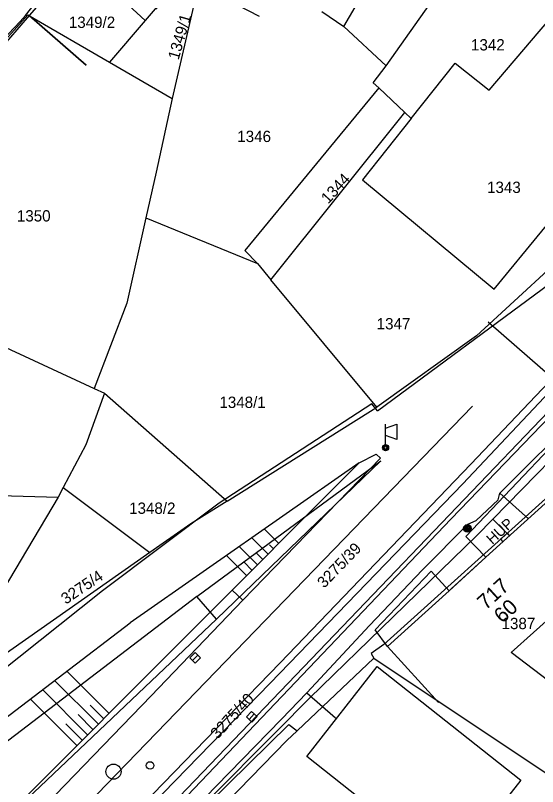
# Model space of a CAD drawing. Extents: x -601580 to 4, y -1204314 to 4.
# Drawn here: x -600174.7 to -600140.2, y -1203683.1 to -1203632.1 of the extents above; entities that cross this region are included whole.
import ezdxf

# ---------------------------------------------------------------- set-up
doc = ezdxf.new("R2010")
doc.units = 0
for name, color, linetype in [('00-INNOGY-NTL', 7, 'Continuous'), ('00-KN-HRANICE PARCEL', 7, 'Continuous'), ('00-KN-PARC. CISLA', 7, 'Continuous'), ('00-KN-VNITRNI KRESBA', 7, 'Continuous'), ('00-POLOHOPIS', 7, 'Continuous'), ('00-SITE KOM. KABEL', 7, 'Continuous'), ('00-VAK-KANAL-POTRUBI', 7, 'Continuous'), ('00-VAK-VODA-RAD IGIS', 7, 'Continuous'), ('Vrstva 25', 7, 'Continuous'), ('Vrstva 27', 7, 'Continuous'), ('Vrstva 28', 7, 'Continuous'), ('Vrstva 33', 7, 'Continuous')]:
    doc.layers.add(name, color=color, linetype=linetype)

# ---------------------------------------------------------------- blocks, each defined once
blk = doc.blocks.new('6.20_44')
at = {"layer": 'Vrstva 27'}
blk.add_circle((0, 0), 0.5, dxfattribs=at)
blk = doc.blocks.new('6.30_62')
at = {"layer": 'Vrstva 27'}
blk.add_line((-0.25, 0), (0.25, 0), dxfattribs=at)
blk.add_lwpolyline([(-0.25, -0.25), (0.25, -0.25), (0.25, 0.25), (-0.25, 0.25)], close=True, dxfattribs=at)
blk = doc.blocks.new('6.30_64')
at = {"layer": 'Vrstva 27'}
blk.add_line((-0.25, 0), (0.25, 0), dxfattribs=at)
blk.add_lwpolyline([(-0.249, -0.25), (0.25, -0.249), (0.249, 0.25), (-0.25, 0.249)], close=True, dxfattribs=at)
blk = doc.blocks.new('6.01A_978')
at = {"layer": 'Vrstva 25'}
for radius in [0.25, 0.2, 0.15, 0.1, 0.05]:
    blk.add_circle((0, 0), radius, dxfattribs=at)
blk = doc.blocks.new('6.790_6')
at = {"layer": 'Vrstva 33'}
blk.add_line((0, 0.2), (0, 1.55), dxfattribs=at)
blk.add_lwpolyline([(0, 1.3), (0.75, 1.55), (0.75, 0.55), (0, 0.8)], dxfattribs=at)
for radius in [0.2, 0.145, 0.0876]:
    blk.add_circle((0, 0), radius, dxfattribs=at)
blk = doc.blocks.new('6.14A_522')
at = {"layer": 'Vrstva 28'}
blk.add_circle((0, 0), 0.25, dxfattribs=at)

msp = doc.modelspace()

# ---------------------------------------------------------------- linework, layer by layer
at = {"layer": '00-INNOGY-NTL'}
for p, q in [((-600136.43, -1203658.56), (-600143.48, -1203652.41)), ((-600143.17, -1203665.46), (-600142.12, -1203666.48))]:
    msp.add_line(p, q, dxfattribs=at)
msp.add_lwpolyline([(-600200.95, -1203725.85), (-600196.18, -1203720.42), (-600193.88, -1203717.79), (-600186.44, -1203709.69), (-600186.02, -1203709.24), (-600180.47, -1203703.4), (-600170.3, -1203692.68), (-600170.15, -1203692.52), (-600164.54, -1203686.62), (-600164.32, -1203686.4), (-600162.46, -1203684.51), (-600162.1, -1203684.15), (-600157.4, -1203679.43), (-600155.29, -1203677.3), (-600144.23, -1203666.53), (-600143.17, -1203665.46), (-600136.43, -1203658.56)], dxfattribs=at)
at = {"layer": '00-KN-HRANICE PARCEL'}
for p, q in [((-600162.01, -1203627.4), (-600164.38, -1203637.6)), ((-600150.21, -1203635.45), (-600144.37, -1203627.17)), ((-600166.16, -1203632.44), (-600170.63, -1203628.32)), ((-600164.22, -1203630.17), (-600166.16, -1203632.44)), ((-600173.93, -1203632.06), (-600185.82, -1203645.47)), ((-600173.93, -1203632.06), (-600168.52, -1203635.2)), ((-600154.48, -1203631.86), (-600153.01, -1203632.85)), ((-600166.16, -1203632.44), (-600168.52, -1203635.2)), ((-600153.01, -1203632.85), (-600150.21, -1203635.45)), ((-600168.52, -1203635.2), (-600164.38, -1203637.6)), ((-600148.98, -1203638.54), (-600150.71, -1203636.91)), ((-600157.84, -1203649.61), (-600148.98, -1203638.54)), ((-600148.98, -1203638.54), (-600148.56, -1203638.94)), ((-600166.11, -1203645.51), (-600167.38, -1203651.16)), ((-600166.11, -1203645.51), (-600158.73, -1203648.54)), ((-600158.73, -1203648.54), (-600157.84, -1203649.61)), ((-600139.25, -1203648.73), (-600144.24, -1203653.31)), ((-600150.83, -1203658.04), (-600157.84, -1203649.61)), ((-600167.38, -1203651.16), (-600169.54, -1203656.81)), ((-600144.24, -1203653.31), (-600150.83, -1203658.04)), ((-600168.84, -1203657.12), (-600170.09, -1203660.52)), ((-600169.54, -1203656.81), (-600168.84, -1203657.12)), ((-600168.84, -1203657.12), (-600160.73, -1203664.25)), ((-600170.09, -1203660.52), (-600171.58, -1203663.36)), ((-600171.58, -1203663.36), (-600171.92, -1203664)), ((-600171.58, -1203663.36), (-600165.85, -1203667.66)), ((-600165.85, -1203667.66), (-600181.89, -1203678.92)), ((-600162.74, -1203670.57), (-600199.85, -1203698.89)), ((-600161.44, -1203672.08), (-600162.74, -1203670.57)), ((-600195.59, -1203704.46), (-600161.44, -1203672.08)), ((-600151.04, -1203674.64), (-600156.1, -1203679.45))]:
    msp.add_line(p, q, dxfattribs=at)
for points in [[(-600148.56, -1203638.94), (-600145.65, -1203635.27), (-600143.4, -1203637.06), (-600138.31, -1203631.06)], [(-600148.56, -1203638.94), (-600151.79, -1203642.99), (-600143.07, -1203650.23), (-600136.77, -1203642.56), (-600138.82, -1203640.83), (-600133.83, -1203634.63)], [(-600150.71, -1203636.91), (-600151.07, -1203636.57), (-600150.21, -1203635.45)], [(-600150.71, -1203636.91), (-600159.57, -1203647.66), (-600158.73, -1203648.54)], [(-600164.38, -1203637.6), (-600165.43, -1203642.49), (-600166.11, -1203645.51)], [(-600185.82, -1203645.47), (-600185.53, -1203645.67), (-600176.3, -1203653.67), (-600169.54, -1203656.81)], [(-600160.73, -1203664.25), (-600151.26, -1203658.31), (-600150.83, -1203658.04)], [(-600162.74, -1203670.57), (-600150.57, -1203661.58), (-600161.44, -1203672.08)], [(-600194.85, -1203661.79), (-600187.88, -1203663.53), (-600185.06, -1203663.61), (-600171.92, -1203664)], [(-600171.92, -1203664), (-600176.84, -1203672.24), (-600181.89, -1203678.92)], [(-600160.73, -1203664.25), (-600163.13, -1203665.75), (-600165.85, -1203667.66)], [(-600139.09, -1203664.18), (-600139.46, -1203663.9), (-600150.38, -1203673.74), (-600151.22, -1203674.34), (-600151.04, -1203674.64)], [(-600151.04, -1203674.64), (-600132.68, -1203686.89), (-600131.82, -1203687.3)], [(-600165.95, -1203688.2), (-600156.65, -1203679.03), (-600156.1, -1203679.45)], [(-600156.1, -1203679.45), (-600156.78, -1203680.09), (-600162.34, -1203685.81)]]:
    msp.add_lwpolyline(points, dxfattribs=at)
at = {"layer": '00-KN-VNITRNI KRESBA'}
for p, q in [((-600153.01, -1203632.85), (-600148.08, -1203624.29)), ((-600141.94, -1203674.28), (-600138.94, -1203671.57)), ((-600130.54, -1203683.01), (-600141.94, -1203674.28)), ((-600155.47, -1203681.16), (-600150.81, -1203675.2)), ((-600150.81, -1203675.2), (-600141.32, -1203682.73)), ((-600145.99, -1203688.65), (-600155.47, -1203681.16)), ((-600141.32, -1203682.73), (-600145.99, -1203688.65))]:
    msp.add_line(p, q, dxfattribs=at)
at = {"layer": '00-POLOHOPIS'}
for p, q in [((-600152.083, -1203671.494), (-600127.322, -1203645.59)), ((-600150.797, -1203658.279), (-600139.392, -1203649.848)), ((-600144.943, -1203666.591), (-600136.321, -1203657.507)), ((-600151.165, -1203657.815), (-600161.256, -1203664.401)), ((-600150.797, -1203658.279), (-600151.165, -1203657.815)), ((-600152.009, -1203661.729), (-600150.874, -1203661.14)), ((-600150.874, -1203661.14), (-600150.587, -1203661.418)), ((-600175.469, -1203685.226), (-600152.009, -1203661.729)), ((-600152.009, -1203661.729), (-600167.146, -1203672.304)), ((-600159.698, -1203670.818), (-600150.587, -1203661.418)), ((-600161.256, -1203664.401), (-600168.987, -1203670.189)), ((-600158.27, -1203666.103), (-600157.322, -1203667.054)), ((-600159.103, -1203666.685), (-600158.03, -1203667.76)), ((-600143.617, -1203667.975), (-600144.943, -1203666.591)), ((-600142.665, -1203666.771), (-600142.221, -1203666.368)), ((-600142.665, -1203666.771), (-600142.497, -1203666.956)), ((-600142.221, -1203666.368), (-600142.053, -1203666.553)), ((-600159.935, -1203667.266), (-600158.738, -1203668.467)), ((-600157.942, -1203667.141), (-600157.676, -1203667.407)), ((-600160.768, -1203667.848), (-600159.446, -1203669.173)), ((-600158.774, -1203667.722), (-600158.384, -1203668.114)), ((-600159.606, -1203668.304), (-600159.092, -1203668.82)), ((-600145.909, -1203670.065), (-600143.86, -1203668.197)), ((-600150.934, -1203672.777), (-600147.242, -1203668.895)), ((-600147.242, -1203668.895), (-600146.057, -1203670.2)), ((-600168.987, -1203670.189), (-600197.659, -1203693.013)), ((-600160.406, -1203670.14), (-600159.698, -1203670.818)), ((-600165.764, -1203677.154), (-600159.698, -1203670.818)), ((-600171.308, -1203691.512), (-600152.083, -1203671.494)), ((-600197.017, -1203695.085), (-600167.146, -1203672.304)), ((-600150.123, -1203673.886), (-600150.934, -1203672.777)), ((-600171.348, -1203675.509), (-600168.553, -1203678.299)), ((-600172.15, -1203676.121), (-600169.26, -1203679.007)), ((-600172.953, -1203676.733), (-600169.966, -1203679.714)), ((-600177.308, -1203689.093), (-600165.764, -1203677.154)), ((-600173.755, -1203677.345), (-600170.673, -1203680.422)), ((-600169.797, -1203677.764), (-600168.906, -1203678.653)), ((-600170.6, -1203678.376), (-600169.613, -1203679.361)), ((-600171.402, -1203678.988), (-600170.32, -1203680.068))]:
    msp.add_line(p, q, dxfattribs=at)
for points in [[(-600165.446, -1203631.705), (-600162.164, -1203627.933), (-600165.76, -1203624.804), (-600166.715, -1203623.982), (-600173.822, -1203632.119), (-600170.056, -1203635.408)], [(-600158.598, -1203632.178), (-600160.768, -1203631.039), (-600159.628, -1203628.87), (-600155.361, -1203631.111)], [(-600170.056, -1203635.408), (-600173.822, -1203632.119), (-600179.313, -1203638.473), (-600180.052, -1203639.316), (-600185.528, -1203645.766), (-600181.716, -1203649.002)], [(-600135.878, -1203667.693), (-600139.244, -1203663.995), (-600143.617, -1203667.975), (-600146.057, -1203670.2), (-600150.123, -1203673.886), (-600146.765, -1203677.59)]]:
    msp.add_lwpolyline(points, dxfattribs=at)
at = {"layer": '00-SITE KOM. KABEL'}
for points in [[(-600186.19, -1203645.96), (-600185.9, -1203645.52), (-600184.47, -1203643.59), (-600182.44, -1203641.45), (-600180.7, -1203639.55), (-600179.25, -1203637.62), (-600178.27, -1203636.55), (-600174.42, -1203632.51), (-600174.07, -1203632.11), (-600169.52, -1203626.32), (-600165.84, -1203622.35), (-600165.69, -1203622.18), (-600160.56, -1203626.28), (-600158.97, -1203627.22)], [(-600170.81, -1203691.52), (-600163.35, -1203683.75), (-600145.94, -1203665.46), (-600115.4, -1203633.77)], [(-600142.69, -1203663.74), (-600137.34, -1203658.38), (-600136.25, -1203657.13), (-600134.44, -1203655.13)], [(-600155.47, -1203676.94), (-600151.31, -1203672.49), (-600147.82, -1203668.81), (-600144.81, -1203665.79), (-600144.27, -1203665.54), (-600142.8, -1203664.17), (-600142.69, -1203663.74)], [(-600140.81, -1203665.43), (-600142.69, -1203663.74)], [(-600144.27, -1203665.54), (-600142.8, -1203664.17)], [(-600147.82, -1203668.81), (-600144.81, -1203665.79)], [(-600155.47, -1203676.94), (-600151.31, -1203672.49)], [(-600164.69, -1203686.46), (-600161.47, -1203683.12), (-600157.15, -1203678.68), (-600155.47, -1203676.94)], [(-600157.15, -1203678.68), (-600155.47, -1203676.94)], [(-600155.47, -1203676.94), (-600153.57, -1203678.59)], [(-600167.89, -1203689.88), (-600164.69, -1203686.46), (-600161.47, -1203683.12), (-600157.15, -1203678.68)]]:
    msp.add_lwpolyline(points, dxfattribs=at)
at = {"layer": '00-VAK-KANAL-POTRUBI'}
msp.add_lwpolyline([(-600144.5, -1203657.98), (-600187.002, -1203701.892)], dxfattribs=at)
at = {"layer": '00-VAK-VODA-RAD IGIS'}
for points in [[(-600071.063, -1203584.227), (-600074.02, -1203587.57), (-600082.15, -1203596.33), (-600094.8, -1203609.48), (-600107.54, -1203622.42), (-600119.79, -1203635.42), (-600132.13, -1203648.68), (-600144.62, -1203661.82), (-600157.22, -1203674.96), (-600169.87, -1203688), (-600178.36, -1203696.67), (-600190.86, -1203709.88), (-600198.98, -1203718.66), (-600207.1, -1203727.65), (-600215.03, -1203736.89), (-600226.38, -1203750.64), (-600226.92, -1203751.09)], [(-600070.963, -1203585.101), (-600075.43, -1203589.86), (-600083, -1203597.91), (-600095.42, -1203610.79), (-600108.07, -1203623.63), (-600120.6, -1203636.97), (-600132.94, -1203650.15), (-600145.14, -1203663.11), (-600157.9, -1203676.31), (-600170.46, -1203689.24), (-600178.64, -1203697.86), (-600191.3, -1203710.97), (-600199.46, -1203719.8), (-600207.54, -1203728.87), (-600215.34, -1203737.96), (-600219.35, -1203742.8)]]:
    msp.add_lwpolyline(points, dxfattribs=at)

# ---------------------------------------------------------------- block references
at = {"layer": '00-POLOHOPIS'}
for name, p in [('6.790_6', (-600150.255, -1203660.723)), ('6.14A_522', (-600165.835, -1203681.753))]:
    msp.add_blockref(name, p, dxfattribs=at)
at = {"layer": '00-POLOHOPIS', "rotation": -90.00000000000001}
for name, p in [('6.01A_978', (-600144.843, -1203666.06)), ('6.20_44', (-600168.252, -1203682.161))]:
    msp.add_blockref(name, p, dxfattribs=at)
at = {"layer": '00-POLOHOPIS'}
for name, p, xscale, yscale, rotation in [('6.30_62', (-600162.846, -1203674.62), 1.0000017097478, 1.0000017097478, 44.96604135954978), ('6.30_64', (-600159.108, -1203678.523), 0.99999872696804, 0.9999987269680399, -132.80346349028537)]:
    msp.add_blockref(name, p, dxfattribs=dict(at, xscale=xscale, yscale=yscale, rotation=rotation))

# ---------------------------------------------------------------- texts
at = {"layer": '00-KN-PARC. CISLA'}
for s, p in [('1349/2', (-600171.209, -1203632.939)), ('1342', (-600144.605, -1203634.43)), ('1346', (-600160.065, -1203640.49)), ('1343', (-600143.545, -1203643.86)), ('1350', (-600174.645, -1203645.75)), ('1347', (-600150.845, -1203652.89)), ('1348/1', (-600161.249, -1203658.09)), ('1348/2', (-600167.221, -1203665.1)), ('1387', (-600142.585, -1203672.73))]:
    msp.add_text(s, height=0.75, dxfattribs=at).set_placement(p)
for s, rotation, p in [('1349/1', 74, (-600163.949, -1203635.094)), ('1344', 47, (-600154.054, -1203644.628)), ('3275/39', 46, (-600154.318, -1203670.06)), ('3275/4', 34, (-600171.408, -1203671.118)), ('3275/40', 47, (-600161.368, -1203680.049))]:
    msp.add_text(s, height=0.75, rotation=rotation, dxfattribs=at).set_placement(p)
at = {"layer": '00-POLOHOPIS'}
for s, height, rotation, p in [('HUP', 0.7, 42.3063, (-600143.196, -1203667.162)), ('717', 1, 42.3612, (-600143.631, -1203671.505)), ('60', 1, 42.3612, (-600142.528, -1203672.394))]:
    msp.add_text(s, height=height, rotation=rotation, dxfattribs=at).set_placement(p)

doc.saveas('drawing.dxf')
